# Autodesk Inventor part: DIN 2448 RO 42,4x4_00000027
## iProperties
Created: 2006-02
Part Number: DIN 2448 RO 42,4x4_00000027
Material: Default
Document SubType Name: Modeling
Designer: FranzK
Stock Number: DIN 2448 RO 42,4x4
Mass: 421.965 g
Surface Area: 2123.47 cm^2
Volume: 421.965 cm^3
Density: 1 g/cm^3
G_L: 890.000 mm
G_W: 42.400 mm
G_H: 42.400 mm
AFG_Item: 42.4 x 4
CSToolsMass: 0.4
CSToolsVolume: 421965.0
CSToolsArea: 2123.0
Author: FranzK
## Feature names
1. AFG_Detailed_DIN 2448 RO 42,4x4_00000027 [Extrusion]
2. AFG_Simplified_DIN 2448 RO 42,4x4_00000027 [Extrusion]
3. AFG_StartExtrusion_1 [Extrusion]
4. AFG_StartExtrusion_2 [Extrusion]
